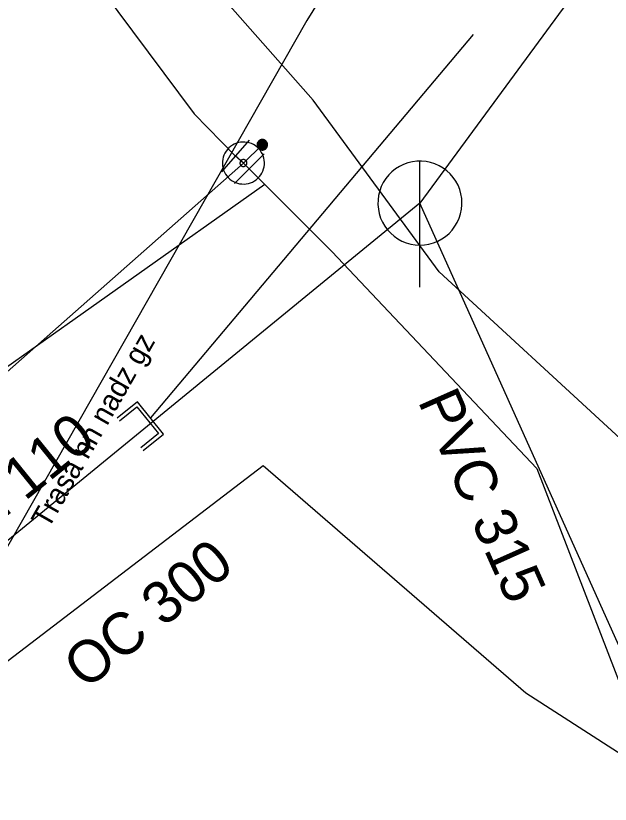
# Model space of a CAD drawing. Extents: x -743072 to -742584, y -978827 to -978325.
# Drawn here: x -742790.44 to -742776.29, y -978604.46 to -978585.7 of the extents above; entities that cross this region are included whole.
import ezdxf

# ---------------------------------------------------------------- set-up
doc = ezdxf.new("R2010")
doc.units = 0
for name, color, linetype in [('IS_CETIN_sdělovací kabel_optika', 7, 'Continuous'), ('IS_CEZ_NN_nadz', 7, 'Continuous'), ('IS_popis_CEZ', 7, 'Continuous'), ('IS_popis_ScVK', 7, 'Continuous'), ('IS_ScVK_Kanal_dest', 7, 'Continuous'), ('IS_ScVK_Kanal_spl', 7, 'Continuous'), ('IS_ScVK_Kanal_šachty', 7, 'Continuous'), ('IS_ScVK_Vodovod', 7, 'Continuous'), ('IS_ScVK_Vodovod_vytyč', 7, 'Continuous')]:
    doc.layers.add(name, color=color, linetype=linetype)

msp = doc.modelspace()

# ---------------------------------------------------------------- linework, layer by layer
at = {"layer": 'IS_CETIN_sdělovací kabel_optika'}
msp.add_lwpolyline([(-742764.74, -978604.1), (-742769, -978601.7), (-742771.75, -978599.72), (-742780.36, -978591.79), (-742783.36, -978587.71), (-742790.25, -978579.9), (-742798.06, -978569.19)], dxfattribs=at)
at = {"layer": 'IS_CEZ_NN_nadz'}
msp.add_lwpolyline([(-742776.65, -978574.74), (-742783.51, -978585.81), (-742799.53, -978613.952)], dxfattribs=at)
at = {"layer": 'IS_ScVK_Kanal_dest'}
for points in [[(-742763.132, -978566.086), (-742780.82, -978590.157)], [(-742785.02, -978589.205), (-742785.215, -978589.035)], [(-742784.881, -978589.342), (-742785.02, -978589.205)], [(-742780.82, -978590.157), (-742796.109, -978602.67)], [(-742787.402, -978596.046), (-742786.919, -978595.656), (-742787.541, -978594.883), (-742788.026, -978595.275)], [(-742787.971, -978595.342), (-742787.554, -978595.006), (-742787.041, -978595.643), (-742787.458, -978595.978)], [(-742836.89, -978635.23), (-742836.829, -978632.584), (-742794.674, -978604.136), (-742784.548, -978596.4), (-742778.303, -978601.806), (-742769.218, -978607.658), (-742757.236, -978613.629), (-742748.697, -978616.71), (-742737.016, -978619.72), (-742706.897, -978621.455), (-742694.704, -978621.477), (-742669.125, -978621.524), (-742647.601, -978624.622), (-742643.224, -978625.196), (-742627.191, -978628.893), (-742614.992, -978632.031), (-742608.58, -978633.224), (-742593.026, -978634.809), (-742583.863, -978635.543)]]:
    msp.add_lwpolyline(points, dxfattribs=at)
at = {"layer": 'IS_ScVK_Kanal_spl'}
for points in [[(-742779.55, -978586.149), (-742787.23, -978595.27)], [(-742774.442, -978604.328), (-742780.82, -978590.157)]]:
    msp.add_lwpolyline(points, dxfattribs=at)
at = {"layer": 'IS_ScVK_Kanal_šachty'}
for points in [[(-742779.82, -978590.157), (-742779.825, -978590.048), (-742779.843, -978589.94), (-742779.873, -978589.834), (-742779.913, -978589.733), (-742779.965, -978589.636), (-742780.027, -978589.546), (-742780.099, -978589.463), (-742780.179, -978589.389), (-742780.267, -978589.323), (-742780.361, -978589.268), (-742780.461, -978589.223), (-742780.566, -978589.19), (-742780.673, -978589.168), (-742780.782, -978589.158), (-742780.892, -978589.16), (-742781, -978589.174), (-742781.107, -978589.199), (-742781.21, -978589.236), (-742781.308, -978589.285), (-742781.4, -978589.343), (-742781.486, -978589.412), (-742781.563, -978589.489), (-742781.632, -978589.575), (-742781.691, -978589.667), (-742781.739, -978589.765), (-742781.776, -978589.868), (-742781.802, -978589.975), (-742781.816, -978590.083), (-742781.819, -978590.193), (-742781.809, -978590.302), (-742781.788, -978590.409), (-742781.754, -978590.513), (-742781.71, -978590.613), (-742781.655, -978590.708), (-742781.589, -978590.796), (-742781.515, -978590.876), (-742781.432, -978590.948), (-742781.342, -978591.01), (-742781.246, -978591.062), (-742781.144, -978591.103), (-742781.039, -978591.133), (-742780.931, -978591.151), (-742780.821, -978591.157), (-742780.712, -978591.151), (-742780.604, -978591.133), (-742780.499, -978591.104), (-742780.397, -978591.063), (-742780.3, -978591.011), (-742780.21, -978590.949), (-742780.127, -978590.878), (-742780.052, -978590.798), (-742779.987, -978590.71), (-742779.931, -978590.616), (-742779.887, -978590.516), (-742779.853, -978590.412), (-742779.831, -978590.304), (-742779.821, -978590.195), (-742779.82, -978590.157)], [(-742780.82, -978592.157), (-742780.819, -978589.157)]]:
    msp.add_lwpolyline(points, dxfattribs=at)
at = {"layer": 'IS_ScVK_Vodovod'}
for points in [[(-742800.784, -978568.611), (-742797.865, -978572.386), (-742786.193, -978588.033), (-742785.215, -978589.035)], [(-742784.886, -978588.657), (-742785.543, -978589.411)], [(-742784.93, -978588.713), (-742784.982, -978588.706), (-742785.034, -978588.705), (-742785.086, -978588.71), (-742785.137, -978588.719), (-742785.188, -978588.734), (-742785.236, -978588.754), (-742785.282, -978588.78), (-742785.325, -978588.809), (-742785.364, -978588.843), (-742785.401, -978588.881), (-742785.433, -978588.923), (-742785.459, -978588.968), (-742785.482, -978589.015), (-742785.499, -978589.064), (-742785.511, -978589.115), (-742785.518, -978589.167), (-742785.519, -978589.219), (-742785.515, -978589.272), (-742785.505, -978589.322), (-742785.49, -978589.373), (-742785.47, -978589.421), (-742785.444, -978589.468), (-742785.415, -978589.511), (-742785.381, -978589.55), (-742785.343, -978589.586), (-742785.301, -978589.618), (-742785.256, -978589.645), (-742785.209, -978589.667), (-742785.16, -978589.684), (-742785.109, -978589.696), (-742785.057, -978589.703), (-742785.005, -978589.704), (-742784.952, -978589.701), (-742784.902, -978589.69), (-742784.851, -978589.675), (-742784.803, -978589.656), (-742784.757, -978589.63), (-742784.713, -978589.601), (-742784.674, -978589.566), (-742784.638, -978589.528), (-742784.606, -978589.486), (-742784.579, -978589.442), (-742784.557, -978589.394), (-742784.54, -978589.345), (-742784.528, -978589.294), (-742784.521, -978589.242), (-742784.52, -978589.19), (-742784.524, -978589.138), (-742784.534, -978589.087), (-742784.549, -978589.036), (-742784.568, -978588.988), (-742784.594, -978588.942), (-742784.623, -978588.899), (-742784.658, -978588.86), (-742784.696, -978588.823), (-742784.738, -978588.791), (-742784.782, -978588.765), (-742784.83, -978588.742), (-742784.879, -978588.725), (-742784.93, -978588.713)], [(-742784.696, -978588.77), (-742784.696, -978588.783), (-742784.693, -978588.796), (-742784.691, -978588.809), (-742784.686, -978588.821), (-742784.679, -978588.833), (-742784.673, -978588.844), (-742784.664, -978588.854), (-742784.654, -978588.864), (-742784.644, -978588.872), (-742784.634, -978588.879), (-742784.622, -978588.885), (-742784.61, -978588.89), (-742784.597, -978588.893), (-742784.583, -978588.895), (-742784.571, -978588.897), (-742784.558, -978588.896), (-742784.544, -978588.894), (-742784.532, -978588.891), (-742784.519, -978588.886), (-742784.507, -978588.88), (-742784.497, -978588.873), (-742784.487, -978588.865), (-742784.477, -978588.855), (-742784.468, -978588.845), (-742784.462, -978588.834), (-742784.456, -978588.822), (-742784.451, -978588.81), (-742784.448, -978588.797), (-742784.446, -978588.784), (-742784.443, -978588.771), (-742784.445, -978588.758), (-742784.446, -978588.745), (-742784.45, -978588.732), (-742784.455, -978588.72), (-742784.46, -978588.708), (-742784.468, -978588.697), (-742784.475, -978588.687), (-742784.485, -978588.677), (-742784.495, -978588.669), (-742784.507, -978588.662), (-742784.519, -978588.656), (-742784.531, -978588.651), (-742784.544, -978588.648), (-742784.556, -978588.646), (-742784.57, -978588.645), (-742784.583, -978588.645), (-742784.595, -978588.647), (-742784.608, -978588.65), (-742784.62, -978588.655), (-742784.632, -978588.661), (-742784.644, -978588.668), (-742784.654, -978588.676), (-742784.664, -978588.686), (-742784.671, -978588.696), (-742784.679, -978588.707), (-742784.684, -978588.719), (-742784.69, -978588.731), (-742784.693, -978588.744), (-742784.695, -978588.757), (-742784.696, -978588.77)], [(-742784.676, -978588.77), (-742784.676, -978588.781), (-742784.674, -978588.792), (-742784.671, -978588.803), (-742784.668, -978588.813), (-742784.663, -978588.823), (-742784.657, -978588.832), (-742784.649, -978588.841), (-742784.642, -978588.849), (-742784.632, -978588.856), (-742784.624, -978588.862), (-742784.614, -978588.867), (-742784.603, -978588.871), (-742784.593, -978588.874), (-742784.581, -978588.877), (-742784.571, -978588.877), (-742784.559, -978588.877), (-742784.549, -978588.875), (-742784.538, -978588.872), (-742784.527, -978588.868), (-742784.517, -978588.863), (-742784.509, -978588.857), (-742784.5, -978588.85), (-742784.492, -978588.842), (-742784.485, -978588.833), (-742784.478, -978588.824), (-742784.473, -978588.814), (-742784.47, -978588.804), (-742784.467, -978588.793), (-742784.465, -978588.782), (-742784.463, -978588.771), (-742784.463, -978588.76), (-742784.465, -978588.749), (-742784.468, -978588.738), (-742784.473, -978588.728), (-742784.478, -978588.718), (-742784.483, -978588.709), (-742784.49, -978588.7), (-742784.499, -978588.692), (-742784.507, -978588.685), (-742784.517, -978588.679), (-742784.527, -978588.674), (-742784.536, -978588.67), (-742784.548, -978588.667), (-742784.558, -978588.665), (-742784.57, -978588.665), (-742784.581, -978588.664), (-742784.592, -978588.666), (-742784.603, -978588.669), (-742784.612, -978588.673), (-742784.622, -978588.678), (-742784.632, -978588.684), (-742784.641, -978588.691), (-742784.649, -978588.699), (-742784.656, -978588.708), (-742784.661, -978588.717), (-742784.666, -978588.727), (-742784.671, -978588.737), (-742784.674, -978588.748), (-742784.676, -978588.759), (-742784.676, -978588.77)], [(-742784.657, -978588.77), (-742784.657, -978588.779), (-742784.656, -978588.788), (-742784.652, -978588.797), (-742784.649, -978588.805), (-742784.646, -978588.813), (-742784.641, -978588.821), (-742784.634, -978588.828), (-742784.629, -978588.834), (-742784.622, -978588.84), (-742784.614, -978588.845), (-742784.605, -978588.849), (-742784.598, -978588.852), (-742784.588, -978588.855), (-742784.58, -978588.856), (-742784.571, -978588.858), (-742784.561, -978588.857), (-742784.553, -978588.856), (-742784.544, -978588.853), (-742784.536, -978588.85), (-742784.527, -978588.846), (-742784.519, -978588.841), (-742784.512, -978588.835), (-742784.507, -978588.829), (-742784.5, -978588.822), (-742784.495, -978588.814), (-742784.492, -978588.806), (-742784.489, -978588.798), (-742784.485, -978588.789), (-742784.485, -978588.78), (-742784.482, -978588.771), (-742784.483, -978588.762), (-742784.485, -978588.753), (-742784.487, -978588.744), (-742784.49, -978588.736), (-742784.495, -978588.728), (-742784.5, -978588.72), (-742784.505, -978588.713), (-742784.512, -978588.707), (-742784.519, -978588.701), (-742784.527, -978588.696), (-742784.534, -978588.692), (-742784.543, -978588.689), (-742784.551, -978588.686), (-742784.561, -978588.685), (-742784.57, -978588.684), (-742784.578, -978588.684), (-742784.588, -978588.685), (-742784.597, -978588.688), (-742784.605, -978588.691), (-742784.612, -978588.695), (-742784.62, -978588.7), (-742784.627, -978588.706), (-742784.634, -978588.712), (-742784.639, -978588.719), (-742784.644, -978588.727), (-742784.649, -978588.735), (-742784.652, -978588.743), (-742784.654, -978588.752), (-742784.656, -978588.761), (-742784.657, -978588.77)], [(-742784.637, -978588.77), (-742784.637, -978588.777), (-742784.636, -978588.784), (-742784.634, -978588.791), (-742784.632, -978588.797), (-742784.629, -978588.803), (-742784.625, -978588.809), (-742784.62, -978588.815), (-742784.615, -978588.82), (-742784.61, -978588.824), (-742784.603, -978588.828), (-742784.598, -978588.831), (-742784.592, -978588.834), (-742784.585, -978588.835), (-742784.578, -978588.838), (-742784.571, -978588.838), (-742784.563, -978588.838), (-742784.556, -978588.836), (-742784.549, -978588.835), (-742784.544, -978588.832), (-742784.536, -978588.829), (-742784.532, -978588.825), (-742784.526, -978588.821), (-742784.521, -978588.816), (-742784.517, -978588.81), (-742784.512, -978588.804), (-742784.509, -978588.798), (-742784.507, -978588.792), (-742784.505, -978588.785), (-742784.504, -978588.778), (-742784.502, -978588.771), (-742784.502, -978588.764), (-742784.504, -978588.757), (-742784.505, -978588.75), (-742784.509, -978588.744), (-742784.512, -978588.737), (-742784.516, -978588.732), (-742784.519, -978588.726), (-742784.524, -978588.721), (-742784.531, -978588.717), (-742784.536, -978588.713), (-742784.543, -978588.71), (-742784.549, -978588.707), (-742784.556, -978588.705), (-742784.563, -978588.704), (-742784.57, -978588.704), (-742784.576, -978588.704), (-742784.583, -978588.704), (-742784.59, -978588.706), (-742784.597, -978588.709), (-742784.603, -978588.712), (-742784.608, -978588.716), (-742784.615, -978588.72), (-742784.62, -978588.725), (-742784.624, -978588.731), (-742784.627, -978588.736), (-742784.63, -978588.743), (-742784.634, -978588.749), (-742784.634, -978588.756), (-742784.637, -978588.763), (-742784.637, -978588.77)], [(-742785.02, -978589.205), (-742784.57, -978588.77)], [(-742784.617, -978588.77), (-742784.617, -978588.775), (-742784.617, -978588.78), (-742784.615, -978588.785), (-742784.614, -978588.789), (-742784.612, -978588.794), (-742784.608, -978588.798), (-742784.605, -978588.801), (-742784.602, -978588.805), (-742784.598, -978588.808), (-742784.595, -978588.811), (-742784.59, -978588.813), (-742784.585, -978588.815), (-742784.581, -978588.816), (-742784.576, -978588.818), (-742784.571, -978588.818), (-742784.566, -978588.818), (-742784.561, -978588.817), (-742784.556, -978588.816), (-742784.551, -978588.814), (-742784.546, -978588.812), (-742784.543, -978588.809), (-742784.539, -978588.806), (-742784.536, -978588.802), (-742784.532, -978588.799), (-742784.529, -978588.795), (-742784.527, -978588.79), (-742784.526, -978588.786), (-742784.524, -978588.781), (-742784.524, -978588.776), (-742784.522, -978588.771), (-742784.522, -978588.766), (-742784.524, -978588.761), (-742784.524, -978588.756), (-742784.527, -978588.752), (-742784.529, -978588.747), (-742784.532, -978588.743), (-742784.534, -978588.739), (-742784.538, -978588.736), (-742784.541, -978588.733), (-742784.546, -978588.73), (-742784.551, -978588.728), (-742784.554, -978588.726), (-742784.559, -978588.725), (-742784.565, -978588.724), (-742784.57, -978588.724), (-742784.575, -978588.724), (-742784.58, -978588.725), (-742784.585, -978588.725), (-742784.588, -978588.727), (-742784.593, -978588.729), (-742784.598, -978588.732), (-742784.6, -978588.735), (-742784.605, -978588.738), (-742784.607, -978588.742), (-742784.61, -978588.746), (-742784.612, -978588.751), (-742784.615, -978588.755), (-742784.615, -978588.76), (-742784.617, -978588.765), (-742784.617, -978588.77)], [(-742784.597, -978588.77), (-742784.597, -978588.773), (-742784.598, -978588.776), (-742784.597, -978588.778), (-742784.595, -978588.781), (-742784.595, -978588.784), (-742784.593, -978588.786), (-742784.59, -978588.788), (-742784.588, -978588.79), (-742784.587, -978588.792), (-742784.585, -978588.794), (-742784.581, -978588.796), (-742784.578, -978588.797), (-742784.576, -978588.797), (-742784.573, -978588.798), (-742784.571, -978588.798), (-742784.568, -978588.798), (-742784.565, -978588.798), (-742784.561, -978588.797), (-742784.559, -978588.796), (-742784.556, -978588.795), (-742784.554, -978588.793), (-742784.551, -978588.791), (-742784.549, -978588.789), (-742784.549, -978588.787), (-742784.546, -978588.785), (-742784.546, -978588.782), (-742784.544, -978588.779), (-742784.544, -978588.777), (-742784.543, -978588.774), (-742784.541, -978588.771), (-742784.543, -978588.768), (-742784.543, -978588.765), (-742784.544, -978588.762), (-742784.544, -978588.76), (-742784.546, -978588.757), (-742784.548, -978588.755), (-742784.549, -978588.752), (-742784.551, -978588.75), (-742784.554, -978588.749), (-742784.556, -978588.747), (-742784.558, -978588.746), (-742784.561, -978588.745), (-742784.563, -978588.744), (-742784.566, -978588.744), (-742784.57, -978588.743), (-742784.573, -978588.744), (-742784.576, -978588.743), (-742784.578, -978588.745), (-742784.581, -978588.745), (-742784.583, -978588.746), (-742784.585, -978588.748), (-742784.588, -978588.749), (-742784.59, -978588.751), (-742784.592, -978588.754), (-742784.593, -978588.756), (-742784.595, -978588.759), (-742784.595, -978588.761), (-742784.597, -978588.764), (-742784.597, -978588.767), (-742784.597, -978588.77)], [(-742784.578, -978588.77), (-742784.578, -978588.772), (-742784.578, -978588.772), (-742784.576, -978588.772), (-742784.576, -978588.774), (-742784.578, -978588.775), (-742784.576, -978588.775), (-742784.576, -978588.775), (-742784.576, -978588.777), (-742784.576, -978588.777), (-742784.575, -978588.778), (-742784.573, -978588.778), (-742784.573, -978588.778), (-742784.573, -978588.779), (-742784.571, -978588.779), (-742784.571, -978588.779), (-742784.57, -978588.779), (-742784.568, -978588.779), (-742784.568, -978588.778), (-742784.568, -978588.778), (-742784.566, -978588.778), (-742784.566, -978588.777), (-742784.566, -978588.777), (-742784.565, -978588.776), (-742784.565, -978588.776), (-742784.563, -978588.775), (-742784.563, -978588.774), (-742784.561, -978588.773), (-742784.561, -978588.773), (-742784.561, -978588.772), (-742784.561, -978588.771), (-742784.561, -978588.77), (-742784.561, -978588.769), (-742784.561, -978588.769), (-742784.563, -978588.768), (-742784.563, -978588.767), (-742784.563, -978588.766), (-742784.563, -978588.766), (-742784.565, -978588.765), (-742784.565, -978588.765), (-742784.566, -978588.764), (-742784.566, -978588.764), (-742784.568, -978588.763), (-742784.568, -978588.763), (-742784.568, -978588.763), (-742784.57, -978588.763), (-742784.571, -978588.763), (-742784.571, -978588.763), (-742784.571, -978588.763), (-742784.573, -978588.764), (-742784.573, -978588.763), (-742784.575, -978588.765), (-742784.575, -978588.765), (-742784.576, -978588.765), (-742784.576, -978588.765), (-742784.576, -978588.767), (-742784.576, -978588.768), (-742784.576, -978588.769), (-742784.578, -978588.769), (-742784.578, -978588.77), (-742784.578, -978588.77)], [(-742784.527, -978588.987), (-742785.234, -978589.695)], [(-742785.02, -978589.205), (-742797.559, -978600.27)], [(-742785.005, -978589.124), (-742785.014, -978589.122), (-742785.022, -978589.123), (-742785.03, -978589.123), (-742785.039, -978589.125), (-742785.047, -978589.127), (-742785.055, -978589.131), (-742785.063, -978589.135), (-742785.07, -978589.139), (-742785.076, -978589.145), (-742785.082, -978589.151), (-742785.087, -978589.159), (-742785.092, -978589.166), (-742785.095, -978589.173), (-742785.099, -978589.181), (-742785.1, -978589.19), (-742785.102, -978589.199), (-742785.101, -978589.207), (-742785.101, -978589.215), (-742785.099, -978589.224), (-742785.097, -978589.232), (-742785.093, -978589.24), (-742785.089, -978589.248), (-742785.085, -978589.255), (-742785.079, -978589.262), (-742785.073, -978589.267), (-742785.065, -978589.272), (-742785.058, -978589.277), (-742785.051, -978589.28), (-742785.043, -978589.284), (-742785.034, -978589.285), (-742785.025, -978589.287), (-742785.017, -978589.286), (-742785.009, -978589.286), (-742785, -978589.284), (-742784.992, -978589.282), (-742784.984, -978589.279), (-742784.976, -978589.274), (-742784.969, -978589.27), (-742784.962, -978589.264), (-742784.957, -978589.258), (-742784.952, -978589.25), (-742784.947, -978589.243), (-742784.944, -978589.236), (-742784.94, -978589.228), (-742784.939, -978589.219), (-742784.937, -978589.21), (-742784.938, -978589.202), (-742784.938, -978589.194), (-742784.94, -978589.185), (-742784.942, -978589.177), (-742784.945, -978589.169), (-742784.95, -978589.161), (-742784.954, -978589.154), (-742784.96, -978589.148), (-742784.966, -978589.142), (-742784.974, -978589.137), (-742784.981, -978589.132), (-742784.988, -978589.129), (-742784.996, -978589.125), (-742785.005, -978589.124)], [(-742784.881, -978589.342), (-742782.914, -978591.311), (-742778.041, -978596.473), (-742774.837, -978604.776), (-742757.802, -978612.539), (-742750.675, -978615.636), (-742735.708, -978619.127), (-742732.432, -978619.039), (-742708.184, -978620.401), (-742706.491, -978620.342)]]:
    msp.add_lwpolyline(points, dxfattribs=at)
at = {"layer": 'IS_ScVK_Vodovod_vytyč'}
msp.add_line((-742784.508, -978589.716), (-742799.838, -978600.562), dxfattribs=at)

# ---------------------------------------------------------------- texts
at = {"layer": 'IS_popis_CEZ'}
msp.add_text('Trasa nn nadz gz', height=0.5, rotation=60.349, dxfattribs=at).set_placement((-742789.66, -978597.928))
at = {"layer": 'IS_popis_ScVK'}
for s, rotation, p in [('PVC 315 ', 294, (-742780.878, -978594.865)), ('PE 110', 39, (-742791.894, -978598.616)), ('OC 300', 39, (-742788.772, -978601.76))]:
    msp.add_text(s, height=1, rotation=rotation, dxfattribs=at).set_placement(p)

doc.saveas('drawing.dxf')
